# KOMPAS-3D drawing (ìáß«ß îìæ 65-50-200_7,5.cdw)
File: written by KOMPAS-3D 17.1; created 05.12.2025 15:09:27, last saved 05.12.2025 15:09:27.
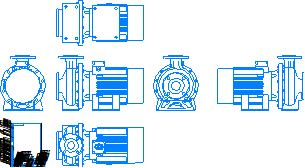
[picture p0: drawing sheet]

Sheet 1: A4, portrait

Title block, sheet 1: name: Насос МНС / 65-50-200_7,5; material: Сталь 10  ГОСТ 1050-88; mass: 174,29; sheets: 1; sheet format: A4

Views: Вид 1, Спереди, Проекционный вид 2, Проекционный вид 3, Проекционный вид 4, Проекционный вид 6
Referenced files in \\adlc.lan\data\АДЛ_ПКД\3D-модели\ADL production\Насосы ГРАНПАМП\Насосы ГРАНПАМП серии МНС\KOMPAS 3D\: Насос МНС 65-50-200_7,5.m3d
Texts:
  Andrey
  АДЛ
Dimensions and other numbers on the sheet: 1:1; 1; 65-50-200_7,5; 174,29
